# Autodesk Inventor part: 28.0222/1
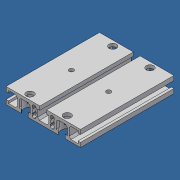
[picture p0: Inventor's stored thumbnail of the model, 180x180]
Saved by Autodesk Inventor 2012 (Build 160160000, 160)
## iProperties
Created: 2007-06
Part Number: 28.0222/1
Material: Aluminum-6061
Document SubType Name: Modeling
Designer: Andy Moles
Density: 2.71 g/cm^3
Description: L = 4.449", MILL TO 28.0222/1
Stock Number: 20.0995 PROFILE 90X19
Mass: 215.513 g
Surface Area: 551.331 cm^2
Volume: 79.525 cm^3
Vendor: F
Author: Andy Moles
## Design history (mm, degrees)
sketch "Sketch1"
  geometry: L1 (18.4, -9.5)-(18.4, -5) reference; L2 (17.9, -5)-(15.7, -5) reference; L3 (15.7, -5)-(15.7, 3.5) reference; L4 (15.7, 3.5)-(18, 5.8) reference; L5 (18, 5.8)-(27, 5.8) reference; L6 (27, 5.8)-(29.3, 3.5) reference; L7 (29.3, 3.5)-(29.3, -5) reference; L8 (26.6, -5)-(26.6, -9.5) reference; L9 (45, -9.5)-(26.9, -9.5) reference; L10 (45, -4.1)-(45, -9.5) reference; L11 (45, -4.1)-(42, -4.1) reference; L12 (42, -4.6)-(42, -6.8) reference; L13 (42, -6.8)-(33.5, -6.8) reference; L14 (33.5, -6.8)-(31.2, -4.5) reference; L15 (31.2, -4.5)-(31.2, 4.5) reference; L16 (31.2, 4.5)-(33.5, 6.8) reference; L17 (33.5, 6.8)-(42, 6.8) reference; L18 (42, 4.1)-(45, 4.1) reference; L19 (45, 9.5)-(45, 4.1) reference; L20 (4.4, 9.5)-(45, 9.5) reference; L21 (4.1, 9.5)-(4.1, 5) reference; L22 (4.6, 5)-(6.8, 5) reference; L23 (6.8, 5)-(6.8, -3.5) reference; L24 (6.8, -3.5)-(4.5, -5.8) reference; L25 (4.5, -5.8)-(-4.5, -5.8) reference; L26 (-4.5, -5.8)-(-6.8, -3.5) reference; L27 (-6.8, -3.5)-(-6.8, 5) reference; L28 (-4.1, 5)-(-4.1, 9.5) reference; L29 (-45, 4.1)-(-45, 9.5) reference; L30 (-45, 4.1)-(-42, 4.1) reference; L31 (-42, 4.1)-(-42, 6.8) reference; L32 (-42, 6.8)-(-33.5, 6.8) reference; L33 (-33.5, 6.8)-(-31.2, 4.5) reference; L34 (-31.2, 4.5)-(-31.2, -4.5) reference; L35 (-31.2, -4.5)-(-33.5, -6.8) reference; L36 (-33.5, -6.8)-(-42, -6.8) reference; L37 (-42, -6.8)-(-42, -4.1) reference; L38 (-42, -4.1)-(-45, -4.1) reference; L39 (-45, -9.5)-(-45, -4.1) reference; L40 (-26.6, -9.5)-(-26.6, -5) reference; L41 (-29.3, -5)-(-29.3, 3.5) reference; L42 (-29.3, 3.5)-(-27, 5.8) reference; L43 (-27, 5.8)-(-18, 5.8) reference; L44 (-18, 5.8)-(-15.7, 3.5) reference; L45 (-15.7, 3.5)-(-15.7, -5) reference; L46 (-15.7, -5)-(-17.9, -5) reference; L47 (-18.4, -5)-(-18.4, -9.5) reference; L48 (-18.1, -9.5)-(-18.4, -9.5) reference; L49 (-26.6, -9.5)-(-45, -9.5) reference; L50 (-17.9, -5)-(-18.4, -5) reference; L51 (-26.6, -5)-(-29.3, -5) reference; L52 (-6.8, 5)-(-4.1, 5) reference; L53 (4.1, 5)-(4.6, 5) reference; L54 (-45, 9.5)-(-4.1, 9.5) reference; L55 (4.1, 9.5)-(4.4, 9.5) reference; L56 (29.3, -5)-(26.6, -5) reference; L57 (18.4, -5)-(17.9, -5) reference; L58 (26.9, -9.5)-(26.6, -9.5) reference; L59 (18.4, -9.5)-(-18.1, -9.5) reference; L60 (42, 6.8)-(42, 4.1) reference; L61 (42, -4.1)-(42, -4.6) reference; L62 (-9.354, -2.59)-(-8.993, -2.95); L63 (-10.7, -7)-(-11.3, -7); L64 (-8.7, -3.657)-(-8.7, -5)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; A1 r 2.5 centre (-11, 0) between (-9.333, -1.863) and (-9.333, 1.863); A2 r 1 centre (-9.7, -3.657) between (-8.7, -3.657) and (-8.993, -2.95); A3 r 2 centre (-10.7, -5) between (-10.7, -7) and (-8.7, -5); A4 r 0.5 centre (-9, -2.236) between (-9.333, -1.863) and (-9.354, -2.59); A5 r 1 centre (-12.3, -3.657) between (-13.007, -2.95) and (-13.3, -3.657); A6 r 2.5 centre (-11, 0) between (-12.667, 1.863) and (-12.667, -1.863); A7 r 2 centre (-11.3, -5) between (-13.3, -5) and (-11.3, -7); A8 r 0.5 centre (-13, -2.236) between (-12.646, -2.59) and (-12.667, -1.863); A9 r 0.5 centre (-13, 2.236) between (-12.667, 1.863) and (-12.646, 2.59); A10 r 2 centre (-11.3, 5) between (-11.3, 7) and (-13.3, 5); A11 r 0.5 centre (-9, 2.236) between (-9.354, 2.59) and (-9.333, 1.863); A12 r 1 centre (-9.7, 3.657) between (-8.993, 2.95) and (-8.7, 3.657); A13 r 2 centre (-10.7, 5) between (-8.7, 5) and (-10.7, 7); A14 r 1 centre (-12.3, 3.657) between (-13.3, 3.657) and (-13.007, 2.95); A15 r 1 centre (12.3, 3.657) between (13.007, 2.95) and (13.3, 3.657); A16 r 0.5 centre (13, 2.236) between (12.646, 2.59) and (12.667, 1.863); A17 r 2 centre (11.3, 5) between (13.3, 5) and (11.3, 7); A18 r 0.5 centre (9, 2.236) between (9.333, 1.863) and (9.354, 2.59); A19 r 1 centre (9.7, 3.657) between (8.7, 3.657) and (8.993, 2.95); A20 r 2 centre (10.7, 5) between (10.7, 7) and (8.7, 5); A21 r 1 centre (9.7, -3.657) between (8.993, -2.95) and (8.7, -3.657); A22 r 2.5 centre (11, 0) between (9.333, 1.863) and (9.333, -1.863); A23 r 0.5 centre (9, -2.236) between (9.354, -2.59) and (9.333, -1.863); A24 r 2 centre (10.7, -5) between (8.7, -5) and (10.7, -7); A25 r 2.5 centre (11, 0) between (12.667, -1.863) and (12.667, 1.863); A26 r 0.5 centre (13, -2.236) between (12.667, -1.863) and (12.646, -2.59); A27 r 1 centre (12.3, -3.657) between (13.3, -3.657) and (13.007, -2.95); A28 r 2 centre (11.3, -5) between (11.3, -7) and (13.3, -5)
  constraints: 162 end point, 56 point on circle, 28 centre point, 28 horizontal, 23 vertical, 71 other
extrude "Extrusion1" new body sketch "Sketch1" stored distance "d0" = 113; taper "d1" = 0 deg
sketch "Sketch2"
  geometry: L1 (0, -113)-(36.8, -113) reference; L2 (63.4, -113)-(63.4, 0) reference; L3 (36.8, 0)-(0, 0) reference; 5 further points
  constraints: 2 horizontal alignment, 2 vertical alignment
  dimensions: "d2" = 113 distance of L1.end L3.start (derived); "d5" = 22.5 distance from line of point (40.9, -6.5) L2; "d6" = 67.5 distance from line of point (-4.1, -6.5) L2; "d14" = 6.5 distance from line of point (40.9, -6.5) L3; "d15" = 6.5 distance from line of point (40.9, -106.5) L1
hole "Hole1" sketch "Sketch2" at (40.9, -6.5), (-4.1, -6.5), (-4.1, -106.5), (40.9, -106.5) diameter "d7" = 9; stored, may be unused: countersink angle "d11" = 90 deg, drill point angle "d13" = 118 deg; dims "d8" = 6, "d9" = 15, "d10" = 15.3, "d12" = 8
sketch "Sketch3"
  geometry: 3 further points
  constraints: 2 horizontal alignment
  dimensions: "d16" = 22.5 distance of point (18.4, -56.5) point (40.9, -56.5); "d17" = 22.5 distance of point (-4.1, -56.5) point (18.4, -56.5)
hole "Hole2" sketch "Sketch3" at (40.9, -56.5), (-4.1, -56.5) diameter "d18" = 5.5; stored, may be unused: countersink angle "d22" = 90 deg, drill point angle "d24" = 118 deg; dims "d19" = 6, "d20" = 9, "d21" = 15.3, "d23" = 8
body "Solid1"
